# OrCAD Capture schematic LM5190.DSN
size C
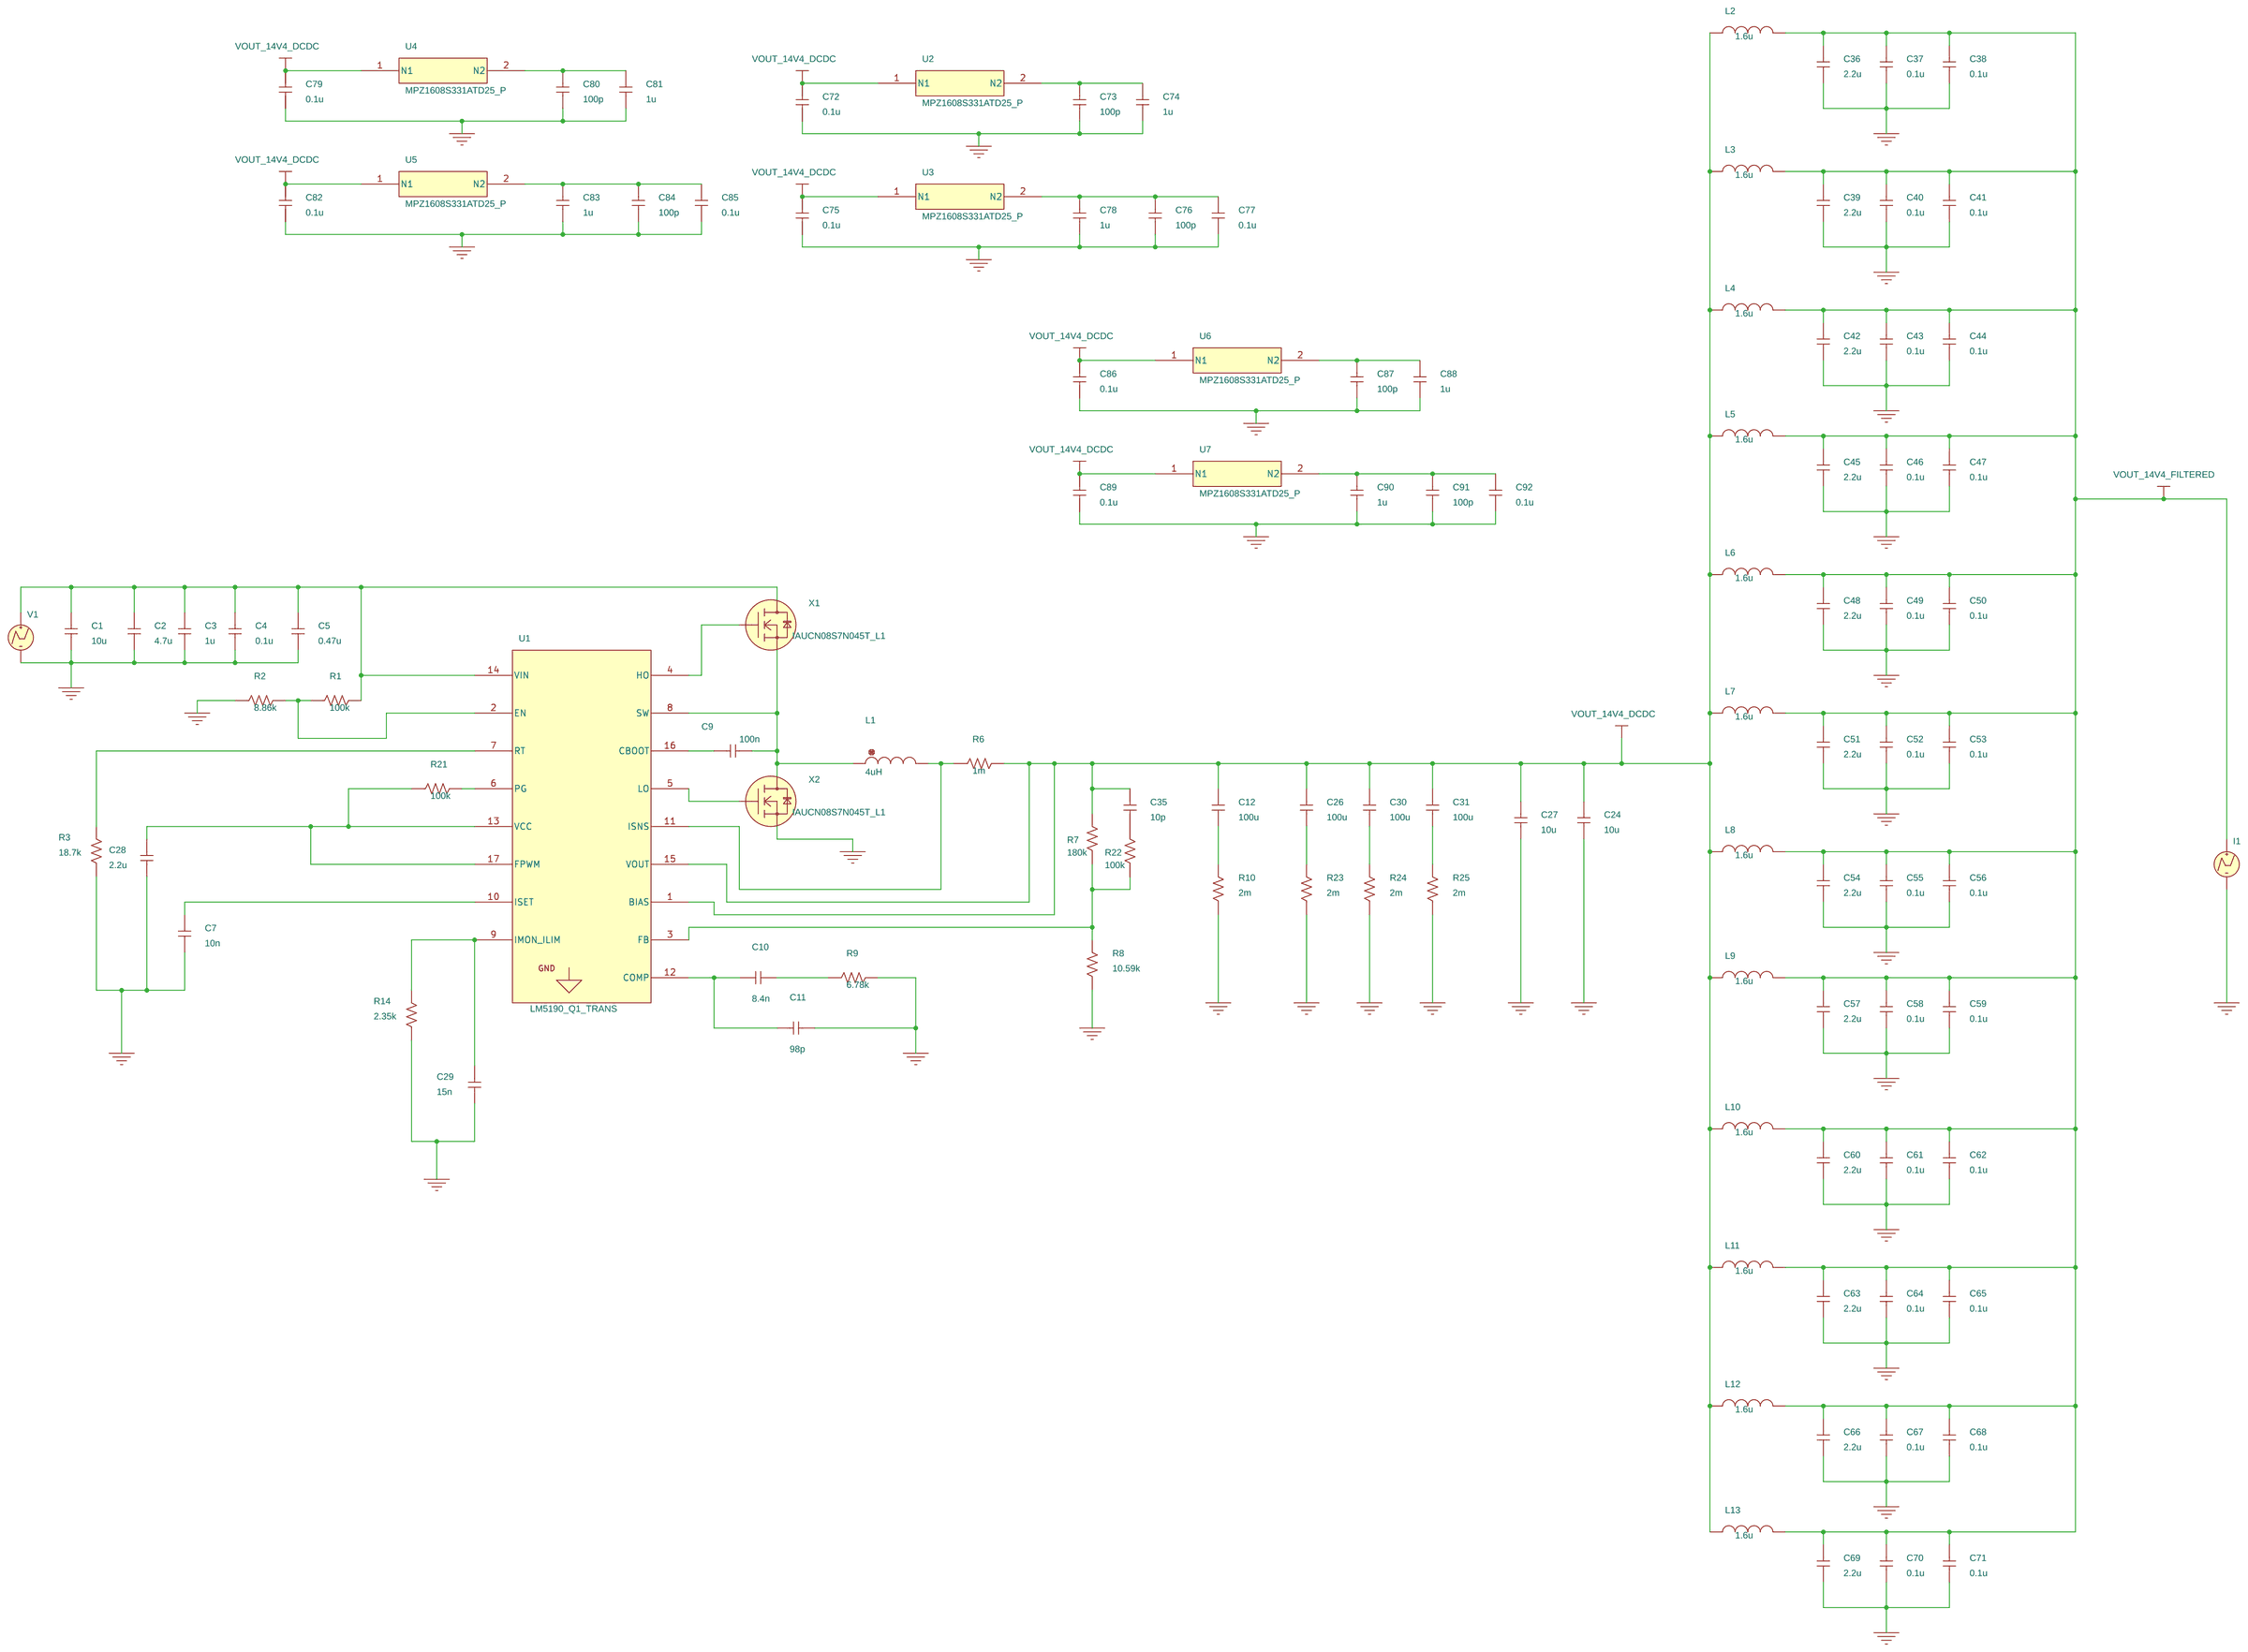
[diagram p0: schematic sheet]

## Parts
C1  10u  [RAD/CK05]
C2  4.7u  [RAD/CK05]
C3  1u  [RAD/CK05]
C4  0.1u  [RAD/CK05]
C5  0.47u  [RAD/CK05]
C7  10n  [RAD/CK05]
C9  100n  [RAD/CK05]
C10  8.4n  [RAD/CK05]
C11  98p  [RAD/CK05]
C12  100u  [RAD/CK05]
C24  10u  [RAD/CK05]
C26  100u  [RAD/CK05]
C27  10u  [RAD/CK05]
C28  2.2u  [RAD/CK05]
C29  15n  [RAD/CK05]
C30  100u  [RAD/CK05]
C31  100u  [RAD/CK05]
C35  10p  [RAD/CK05]
C36  2.2u  [RAD/CK05]
C37  0.1u  [RAD/CK05]
C38  0.1u  [RAD/CK05]
C39  2.2u  [RAD/CK05]
C40  0.1u  [RAD/CK05]
C41  0.1u  [RAD/CK05]
C42  2.2u  [RAD/CK05]
C43  0.1u  [RAD/CK05]
C44  0.1u  [RAD/CK05]
C45  2.2u  [RAD/CK05]
C46  0.1u  [RAD/CK05]
C47  0.1u  [RAD/CK05]
C48  2.2u  [RAD/CK05]
C49  0.1u  [RAD/CK05]
C50  0.1u  [RAD/CK05]
C51  2.2u  [RAD/CK05]
C52  0.1u  [RAD/CK05]
C53  0.1u  [RAD/CK05]
C54  2.2u  [RAD/CK05]
C55  0.1u  [RAD/CK05]
C56  0.1u  [RAD/CK05]
C57  2.2u  [RAD/CK05]
C58  0.1u  [RAD/CK05]
C59  0.1u  [RAD/CK05]
C60  2.2u  [RAD/CK05]
C61  0.1u  [RAD/CK05]
C62  0.1u  [RAD/CK05]
C63  2.2u  [RAD/CK05]
C64  0.1u  [RAD/CK05]
C65  0.1u  [RAD/CK05]
C66  2.2u  [RAD/CK05]
C67  0.1u  [RAD/CK05]
C68  0.1u  [RAD/CK05]
C69  2.2u  [RAD/CK05]
C70  0.1u  [RAD/CK05]
C71  0.1u  [RAD/CK05]
C72  0.1u  [RAD/CK05]
C73  100p  [RAD/CK05]
C74  1u  [RAD/CK05]
C75  0.1u  [RAD/CK05]
C76  100p  [RAD/CK05]
C77  0.1u  [RAD/CK05]
C78  1u  [RAD/CK05]
C79  0.1u  [RAD/CK05]
C80  100p  [RAD/CK05]
C81  1u  [RAD/CK05]
C82  0.1u  [RAD/CK05]
C83  1u  [RAD/CK05]
C84  100p  [RAD/CK05]
C85  0.1u  [RAD/CK05]
C86  0.1u  [RAD/CK05]
C87  100p  [RAD/CK05]
C88  1u  [RAD/CK05]
C89  0.1u  [RAD/CK05]
C90  1u  [RAD/CK05]
C91  100p  [RAD/CK05]
C92  0.1u  [RAD/CK05]
I1  IPWL_GENERIC
L1  4uH  [DISC/.350x.175/LS.200x.100/.034]
L2  1.6u
L3  1.6u
L4  1.6u
L5  1.6u
L6  1.6u
L7  1.6u
L8  1.6u
L9  1.6u
L10  1.6u
L11  1.6u
L12  1.6u
L13  1.6u
R1  100k  [AX/RC05]
R2  8.86k  [AX/RC05]
R3  18.7k  [AX/RC05]
R6  1m  [AX/RC05]
R7  180k  [AX/RC05]
R8  10.59k  [AX/RC05]
R9  6.78k  [AX/RC05]
R10  2m  [AX/RC05]
R14  2.35k  [AX/RC05]
R21  100k  [AX/RC05]
R22  100k  [AX/RC05]
R23  2m  [AX/RC05]
R24  2m  [AX/RC05]
R25  2m  [AX/RC05]
U1  LM5190_Q1_TRANS
U2  MPZ1608S331ATD25_P
U3  MPZ1608S331ATD25_P
U4  MPZ1608S331ATD25_P
U5  MPZ1608S331ATD25_P
U6  MPZ1608S331ATD25_P
U7  MPZ1608S331ATD25_P
V1  VPWL_GENERIC
X1  IAUCN08S7N045T_L1
X2  IAUCN08S7N045T_L1

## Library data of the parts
C1-C5 C7 C9-C12 C24 C26-C31 C35-C92 = C
I1 = IPWL_GENERIC: AppProp: No_reps$POINTS_TYPE_PWL$0$0; FIRST_NPAIRS: 0m 0  3.2m 0  3.22m 0  3.2219m 9.5  3.3924m 9.5  3.4024m 9.5  3.4076m 35.5  3.8076m 35.5  3.8128m 9.5  3.9508m 9.5  4.0508m 9.5  4.0527m 0  4.2432m 0  4.2532m 0  4.2603m 35.5  4.6603m 35.5  4.6674m 0  6m 0; PSpiceTemplate: I^@REFDES %+ %- ?DC|DC @DC| ?AC|AC @AC| PWL ?TSF|TIME_SCALE_FACTOR=@TSF| ?VSF|VALUE_SCALE_FACTOR=@VSF| ?REPEAT_VALUE| \n+ REPEAT FOR @REPEAT_VALUE| \n+ @FIRST_NPAIRS ?SECOND_NPAIRS|\n+ @SECOND_NPAIRS ?THIRD_NPAIRS/\n+ @THIRD_NPAIRS/| ?REPEAT_VALUE| \n+ ENDREPEAT|
L1 = L
L2-L13 = CHSA_P_8090_78433490160_1u6
R1-R3 R6-R10 R14 R21-R25 = R
U1 = LM5190_Q1_TRANS
U2-U7 = MPZ1608S331ATD25_P
V1 = VPWL_GENERIC: AppProp: No_reps$POINTS_TYPE_PWL$0$0; FIRST_NPAIRS: 0 0 0.1m 48 5m 48 6m 48; PSpiceTemplate: V^@REFDES %+ %- ?DC|DC @DC| ?AC|AC @AC| PWL ?TSF|TIME_SCALE_FACTOR=@TSF| ?VSF|VALUE_SCALE_FACTOR=@VSF| ?REPEAT_VALUE| \n+ REPEAT FOR @REPEAT_VALUE| \n+ @FIRST_NPAIRS ?SECOND_NPAIRS|\n+ @SECOND_NPAIRS ?THIRD_NPAIRS/\n+ @THIRD_NPAIRS/| ?REPEAT_VALUE| \n+ ENDREPEAT|
X1 X2 = IAUCN08S7N045T_L1

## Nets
0: C1.1 C2.1 C3.1 C4.1 C5.1 C7.2 C11.1 C24.2 C27.2 C28.1 C29.1 C36.2 C37.2 C38.2 C39.2 C40.2 C41.2 C42.2 C43.2 C44.2 C45.2 C46.2 C47.2 C48.2 C49.2 C50.2 C51.2 C52.2 C53.2 C54.2 C55.2 C56.2 C57.2 C58.2 C59.2 C60.2 C61.2 C62.2 C63.2 C64.2 C65.2 C66.2 C67.2 C68.2 C69.2 C70.2 C71.2 C72.2 C73.2 C74.2 C75.2 C76.2 C77.2 C78.2 C79.2 C80.2 C81.2 C82.2 C83.2 C84.2 C85.2 C86.2 C87.2 C88.2 C89.2 C90.2 C91.2 C92.2 I1.2(-) R2.1 R3.1 R8.1 R9.2 R10.1 R14.1 R23.1 R24.1 R25.1 V1.2(-) X2.3(source)
VOUT_14V4_DCDC: C12.1 C24.1 C26.1 C27.1 C30.1 C31.1 C35.1 C72.1 C75.1 C79.1 C82.1 C86.1 C89.1 L2.1 L3.1 L4.1 L5.1 L6.1 L7.1 L8.1 L9.1 L10.1 L11.1 L12.1 L13.1 R6.2 R7.2 U1.1(BIAS) U1.15(VOUT) U2.1(N1) U3.1(N1) U4.1(N1) U5.1(N1) U6.1(N1) U7.1(N1)
VOUT_14V4_Filtered: C36.1 C37.1 C38.1 C39.1 C40.1 C41.1 C42.1 C43.1 C44.1 C45.1 C46.1 C47.1 C48.1 C49.1 C50.1 C51.1 C52.1 C53.1 C54.1 C55.1 C56.1 C57.1 C58.1 C59.1 C60.1 C61.1 C62.1 C63.1 C64.1 C65.1 C66.1 C67.1 C68.1 C69.1 C70.1 C71.1 I1.1(+) L2.2 L3.2 L4.2 L5.2 L6.2 L7.2 L8.2 L9.2 L10.2 L11.2 L12.2 L13.2
N00215: C1.2 C2.2 C3.2 C4.2 C5.2 R1.2 U1.14(VIN) V1.1(+) X1.1(drain)
N00490: R1.1 R2.2 U1.2(EN)
N00607: R3.2 U1.7(RT)
N00908: C7.1 U1.10(ISET)
N01169: U1.4(HO) X1.2(gate)
N01219: C9.1 L1.1 U1.8(SW) X1.3(source) X2.1(drain)
N01254: C9.2 U1.16(CBOOT)
N01299: U1.5(LO) X2.2(gate)
N01429: L1.2 R6.1 U1.11(ISNS)
N01585: R7.1 R8.2 R22.1 U1.3(FB)
N01803: C10.2 C11.2 U1.12(COMP)
N01820: C10.1 R9.1
N02063: C12.2 R10.2
N23492: C26.2 R23.2
N29163: C28.2 R21.1 U1.13(VCC) U1.17(FPWM)
N29915: C29.2 R14.2 U1.9(IMON_ILIM)
N31971: C30.2 R24.2
N32325: C31.2 R25.2
N35058: R21.2 U1.6(PG)
N41302: C35.2 R22.2
N45701: C73.1 C74.1 U2.2(N2)
N46952: C76.1 C77.1 C78.1 U3.2(N2)
N48287: C80.1 C81.1 U4.2(N2)
N48407: C83.1 C84.1 C85.1 U5.2(N2)
N49075: C87.1 C88.1 U6.2(N2)
N49195: C90.1 C91.1 C92.1 U7.2(N2)
